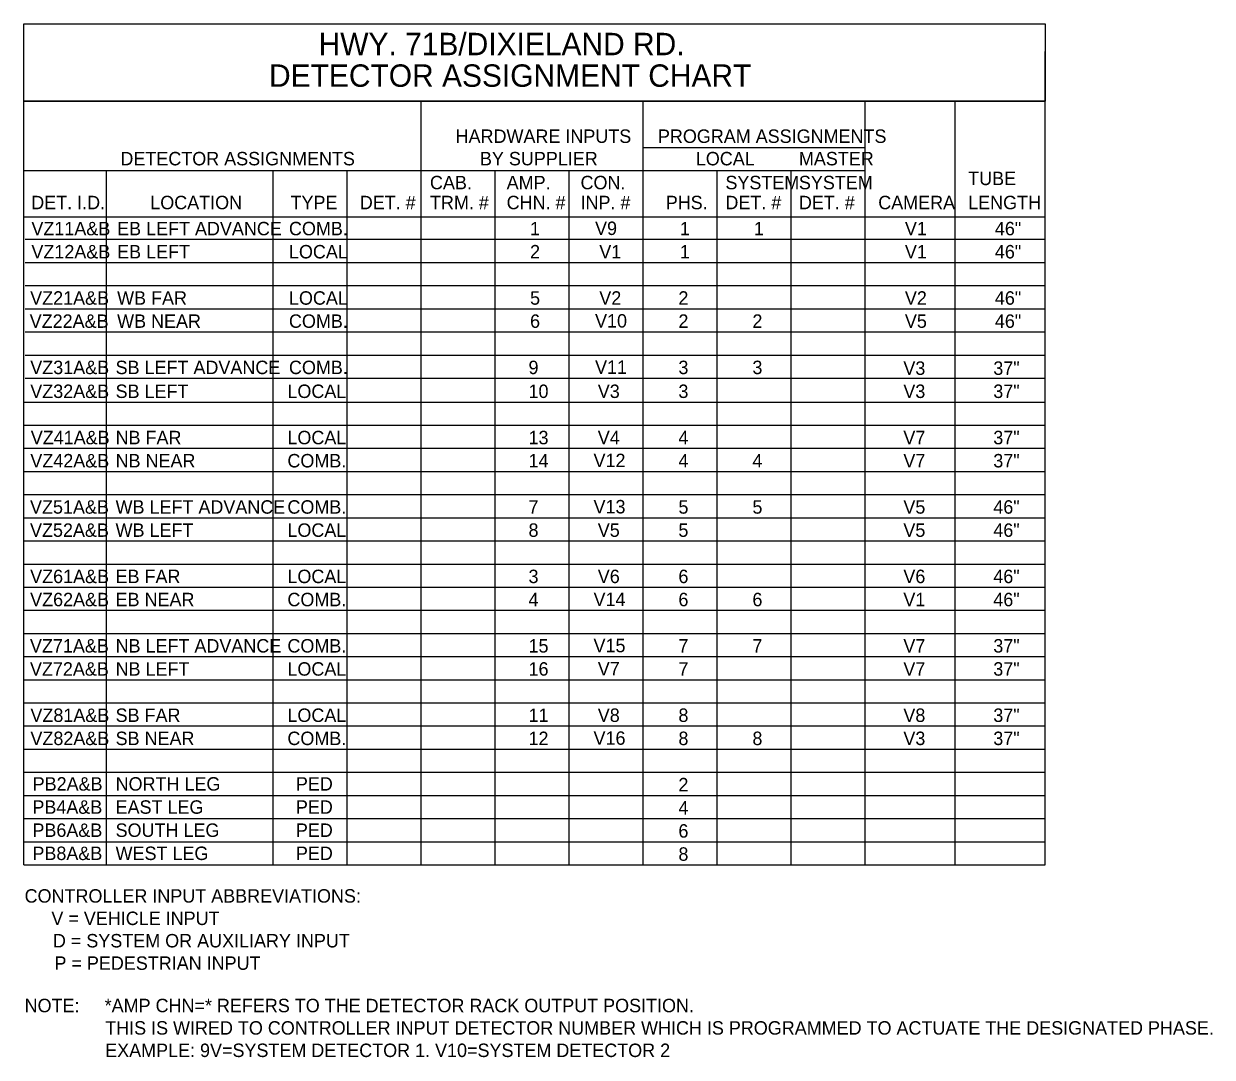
# Model space of a CAD drawing. Extents: x -15.7 to 19.3, y -1.4 to 10.8.
# Drawn here: x -15.71 to -8.64, y -1.45 to 4.7 of the extents above; entities that cross this region are included whole.
import ezdxf

# ---------------------------------------------------------------- set-up
doc = ezdxf.new("R2010")
doc.units = 0
for name, color, linetype in [('TBLBDR', 7, 'Continuous'), ('TBLLINE', 7, 'Continuous'), ('TBLTEXT', 7, 'Continuous'), ('TEXT', 7, 'Continuous'), ('TITEXT', 7, 'Continuous')]:
    doc.layers.add(name, color=color, linetype=linetype)

msp = doc.modelspace()

# ---------------------------------------------------------------- linework, layer by layer
at = {"layer": 'TBLBDR'}
for p, q in [((-15.7146, -0.303), (-15.7146, 4.5377)), ((-9.6309, -0.303), (-9.6309, 4.5377)), ((-15.7146, 4.2424), (-9.6309, 4.2424)), ((-13.3469, -0.303), (-13.3469, 4.2424)), ((-12.0246, -0.303), (-12.0246, 4.2424)), ((-10.7023, -0.303), (-10.7023, 4.2424)), ((-10.1666, -0.303), (-10.1666, 4.2424)), ((-12.0246, 3.9669), (-10.7023, 3.9669)), ((-15.7146, 3.8292), (-10.7023, 3.8292)), ((-15.7146, 3.5537), (-9.6309, 3.5537)), ((-15.7146, 0.2479), (-9.6309, 0.2479)), ((-15.7146, -0.303), (-9.6309, -0.303))]:
    msp.add_line(p, q, dxfattribs=at)
msp.add_lwpolyline([(-15.7146, 4.7035), (-9.6309, 4.7035), (-9.6309, 4.2424), (-15.7146, 4.2424)], close=True, dxfattribs=at)
at = {"layer": 'TBLLINE'}
for p, q in [((-15.2215, -0.303), (-15.2215, 3.8292)), ((-14.2285, -0.303), (-14.2285, 3.8292)), ((-13.7877, -0.303), (-13.7877, 3.8292)), ((-12.9062, -0.303), (-12.9062, 3.8292)), ((-12.4654, -0.303), (-12.4654, 3.8292)), ((-11.5839, -0.303), (-11.5839, 3.8292)), ((-11.1431, -0.303), (-11.1431, 3.8292)), ((-15.7054, 3.4204), (-9.6309, 3.4204)), ((-15.7054, 3.2826), (-9.6309, 3.2826)), ((-15.7054, 3.1449), (-9.6309, 3.1449)), ((-15.7054, 3.0071), (-9.6309, 3.0071)), ((-15.7054, 2.8694), (-9.6309, 2.8694)), ((-15.7054, 2.7317), (-9.6309, 2.7317)), ((-15.7054, 2.5939), (-9.6309, 2.5939)), ((-15.7146, 2.4518), (-9.6309, 2.4518)), ((-15.7146, 2.314), (-9.6309, 2.314)), ((-15.7146, 2.1763), (-9.6309, 2.1763)), ((-15.7146, 2.0385), (-9.6309, 2.0385)), ((-15.7146, 1.9008), (-9.6309, 1.9008)), ((-15.7146, 1.7631), (-9.6309, 1.7631)), ((-15.7146, 1.6253), (-9.6309, 1.6253)), ((-15.7146, 1.4876), (-9.6309, 1.4876)), ((-15.7146, 1.3498), (-9.6309, 1.3498)), ((-15.7146, 1.2121), (-9.6309, 1.2121)), ((-15.7146, 1.0744), (-9.6309, 1.0744)), ((-15.7146, 0.9366), (-9.6309, 0.9366)), ((-15.7146, 0.7989), (-9.6309, 0.7989)), ((-15.7146, 0.6611), (-9.6309, 0.6611)), ((-15.7146, 0.5234), (-9.6309, 0.5234)), ((-15.7146, 0.3857), (-9.6309, 0.3857)), ((-15.7146, 0.1102), (-9.6309, 0.1102)), ((-15.7146, -0.0276), (-9.6309, -0.0276)), ((-15.7146, -0.1653), (-9.6309, -0.1653))]:
    msp.add_line(p, q, dxfattribs=at)

# ---------------------------------------------------------------- texts
at = {"layer": 'TBLTEXT'}
for s, height, p in [('HARDWARE INPUTS', 0.079999, (-13.1425, 3.9943)), ('PROGRAM ASSIGNMENTS', 0.079999, (-11.9375, 3.9943)), ('DETECTOR ASSIGNMENTS', 0.079999, (-15.1389, 3.8607)), ('BY SUPPLIER', 0.079999, (-12.9975, 3.8607)), ('LOCAL', 0.08, (-11.7117, 3.8607)), ('MASTER', 0.08, (-11.0979, 3.8607)), ('TUBE', 0.08, (-10.0896, 3.7431)), ('CAB.', 0.08, (-13.2952, 3.7183)), ('AMP.', 0.08, (-12.8385, 3.7183)), ('CON.', 0.08, (-12.3984, 3.7183)), ('SYSTEM', 0.08, (-11.5355, 3.7183)), ('SYSTEM', 0.08, (-11.0979, 3.7183)), ('DET. I.D.', 0.08, (-15.67, 3.5995)), ('LOCATION', 0.08, (-14.9611, 3.5995)), ('TYPE', 0.08, (-14.1257, 3.5995)), ('DET. #', 0.08, (-13.7131, 3.5995)), ('TRM. #', 0.08, (-13.2952, 3.5995)), ('CHN. #', 0.08, (-12.8385, 3.5995)), ('INP. #', 0.08, (-12.3984, 3.5995)), ('PHS.', 0.08, (-11.8909, 3.5995)), ('DET. #', 0.08, (-11.5355, 3.5995)), ('DET. #', 0.08, (-11.0979, 3.5995)), ('CAMERA', 0.08, (-10.6253, 3.5995)), ('LENGTH', 0.08, (-10.0896, 3.5995)), ('CONTROLLER INPUT ABBREVIATIONS:', 0.079999, (-15.7096, -0.5281)), ('V = VEHICLE INPUT', 0.079999, (-15.5501, -0.6615)), ('D = SYSTEM OR AUXILIARY INPUT', 0.079999, (-15.541, -0.7948)), ('P = PEDESTRIAN INPUT', 0.079999, (-15.5319, -0.9281)), ('NOTE:', 0.08, (-15.7096, -1.1805)), ('*AMP CHN=* REFERS TO THE DETECTOR RACK OUTPUT POSITION.', 0.079999, (-15.2327, -1.1805)), ('THIS IS WIRED TO CONTROLLER INPUT DETECTOR NUMBER WHICH IS PROGRAMMED TO ACTUATE THE DESIGNATED PHASE.', 0.0799994, (-15.2296, -1.3138)), ('EXAMPLE: 9V=SYSTEM DETECTOR 1. V10=SYSTEM DETECTOR 2', 0.079999, (-15.2296, -1.4472))]:
    msp.add_text(s, height=height, dxfattribs=at).set_placement(p)
at = {"layer": 'TEXT'}
for s, height, p in [('VZ11A&B', 0.08, (-15.669, 3.4444)), ('EB LEFT ADVANCE', 0.079999, (-15.1585, 3.4444)), ('COMB.', 0.08, (-14.1351, 3.4444)), ('1', 0.08, (-12.6991, 3.4444)), ('V9', 0.08, (-12.3119, 3.4461)), ('1', 0.08, (-11.8063, 3.4444)), ('1', 0.08, (-11.3655, 3.4444)), ('V1', 0.08, (-10.4665, 3.4444)), ('46"', 0.08, (-9.9307, 3.4444)), ('VZ12A&B', 0.08, (-15.669, 3.3067)), ('EB LEFT', 0.08, (-15.1585, 3.3067)), ('LOCAL', 0.08, (-14.1351, 3.3067)), ('2', 0.08, (-12.6991, 3.3067)), ('V1', 0.08, (-12.2866, 3.3067)), ('1', 0.08, (-11.8063, 3.3067)), ('V1', 0.08, (-10.4665, 3.3067)), ('46"', 0.08, (-9.9307, 3.3067)), ('VZ21A&B', 0.08, (-15.6764, 3.0312)), ('WB FAR', 0.08, (-15.1585, 3.0312)), ('LOCAL', 0.08, (-14.1351, 3.0312)), ('5', 0.08, (-12.6991, 3.0312)), ('V2', 0.08, (-12.2866, 3.0312)), ('2', 0.08, (-11.8154, 3.0312)), ('V2', 0.08, (-10.4665, 3.0312)), ('46"', 0.08, (-9.9307, 3.0312)), ('VZ22A&B', 0.08, (-15.6793, 2.8935)), ('WB NEAR', 0.08, (-15.1585, 2.8935)), ('COMB.', 0.08, (-14.1351, 2.8935)), ('6', 0.08, (-12.6991, 2.8935)), ('V10', 0.08, (-12.3119, 2.8952)), ('2', 0.08, (-11.8154, 2.8935)), ('2', 0.08, (-11.3747, 2.8935)), ('V5', 0.08, (-10.4665, 2.8935)), ('46"', 0.08, (-9.9307, 2.8935)), ('VZ31A&B', 0.08, (-15.6758, 2.618)), ('SB LEFT ADVANCE', 0.079999, (-15.1676, 2.618)), ('COMB.', 0.08, (-14.1351, 2.618)), ('9', 0.08, (-12.7082, 2.618)), ('V11', 0.08, (-12.3119, 2.6197)), ('3', 0.08, (-11.8154, 2.618)), ('3', 0.08, (-11.3747, 2.618)), ('V3', 0.08, (-10.4756, 2.6136)), ('37"', 0.08, (-9.9399, 2.6136)), ('VZ32A&B', 0.08, (-15.6758, 2.4759)), ('SB LEFT', 0.08, (-15.1676, 2.4759)), ('LOCAL', 0.08, (-14.1442, 2.4759)), ('10', 0.08, (-12.7082, 2.4759)), ('V3', 0.08, (-12.2957, 2.4759)), ('3', 0.08, (-11.8154, 2.4759)), ('V3', 0.08, (-10.4756, 2.4759)), ('37"', 0.08, (-9.9399, 2.4759)), ('VZ41A&B', 0.08, (-15.6728, 2.2004)), ('NB FAR', 0.08, (-15.1676, 2.2004)), ('LOCAL', 0.08, (-14.1442, 2.2004)), ('13', 0.08, (-12.7082, 2.2004)), ('V4', 0.08, (-12.2957, 2.2004)), ('4', 0.08, (-11.8154, 2.2004)), ('V7', 0.08, (-10.4756, 2.2004)), ('37"', 0.08, (-9.9399, 2.2004)), ('VZ42A&B', 0.08, (-15.6755, 2.0626)), ('NB NEAR', 0.08, (-15.1676, 2.0626)), ('COMB.', 0.08, (-14.1442, 2.0626)), ('14', 0.08, (-12.7082, 2.0626)), ('V12', 0.08, (-12.3211, 2.0643)), ('4', 0.08, (-11.8154, 2.0626)), ('4', 0.08, (-11.3747, 2.0626)), ('V7', 0.08, (-10.4756, 2.0626)), ('37"', 0.08, (-9.9399, 2.0626)), ('VZ51A&B', 0.08, (-15.6773, 1.7872)), ('WB LEFT ADVANCE', 0.079999, (-15.1676, 1.7872)), ('COMB.', 0.08, (-14.1442, 1.7872)), ('7', 0.08, (-12.7082, 1.7872)), ('V13', 0.08, (-12.3211, 1.7889)), ('5', 0.08, (-11.8154, 1.7872)), ('5', 0.08, (-11.3747, 1.7872)), ('V5', 0.08, (-10.4756, 1.7872)), ('46"', 0.08, (-9.9399, 1.7872)), ('VZ52A&B', 0.08, (-15.6773, 1.6494)), ('WB LEFT', 0.08, (-15.1676, 1.6494)), ('LOCAL', 0.08, (-14.1442, 1.6494)), ('8', 0.08, (-12.7082, 1.6494)), ('V5', 0.08, (-12.2957, 1.6494)), ('5', 0.08, (-11.8154, 1.6494)), ('V5', 0.08, (-10.4756, 1.6494)), ('46"', 0.08, (-9.9399, 1.6494)), ('VZ61A&B', 0.08, (-15.6766, 1.3739)), ('EB FAR', 0.08, (-15.1676, 1.3739)), ('LOCAL', 0.08, (-14.1442, 1.3739)), ('3', 0.08, (-12.7082, 1.3739)), ('V6', 0.08, (-12.2957, 1.3739)), ('6', 0.08, (-11.8154, 1.3739)), ('V6', 0.08, (-10.4756, 1.3739)), ('46"', 0.08, (-9.9399, 1.3739)), ('VZ62A&B', 0.08, (-15.6766, 1.2362)), ('EB NEAR', 0.08, (-15.1676, 1.2362)), ('COMB.', 0.08, (-14.1442, 1.2362)), ('4', 0.08, (-12.7082, 1.2362)), ('V14', 0.08, (-12.3211, 1.2379)), ('6', 0.08, (-11.8154, 1.2362)), ('6', 0.08, (-11.3747, 1.2362)), ('V1', 0.08, (-10.4756, 1.2362)), ('46"', 0.08, (-9.9399, 1.2362)), ('VZ71A&B', 0.08, (-15.6777, 0.9607)), ('NB LEFT ADVANCE', 0.079999, (-15.1676, 0.9607)), ('COMB.', 0.08, (-14.1442, 0.9607)), ('15', 0.08, (-12.7082, 0.9607)), ('V15', 0.08, (-12.3211, 0.9624)), ('7', 0.08, (-11.8154, 0.9607)), ('7', 0.08, (-11.3747, 0.9607)), ('V7', 0.08, (-10.4756, 0.9607)), ('37"', 0.08, (-9.9399, 0.9607)), ('VZ72A&B', 0.08, (-15.6777, 0.823)), ('NB LEFT', 0.08, (-15.1676, 0.823)), ('LOCAL', 0.08, (-14.1442, 0.823)), ('16', 0.08, (-12.7082, 0.823)), ('V7', 0.08, (-12.2957, 0.8247)), ('7', 0.08, (-11.8154, 0.823)), ('V7', 0.08, (-10.4756, 0.823)), ('37"', 0.08, (-9.9399, 0.823)), ('VZ81A&B', 0.08, (-15.6749, 0.5475)), ('SB FAR', 0.08, (-15.1676, 0.5475)), ('LOCAL', 0.08, (-14.1442, 0.5475)), ('11', 0.08, (-12.7082, 0.5475)), ('V8', 0.08, (-12.2957, 0.5475)), ('8', 0.08, (-11.8154, 0.5475)), ('V8', 0.08, (-10.4756, 0.5475)), ('37"', 0.08, (-9.9399, 0.5475)), ('VZ82A&B', 0.08, (-15.6749, 0.4098)), ('SB NEAR', 0.08, (-15.1676, 0.4098)), ('COMB.', 0.08, (-14.1442, 0.4098)), ('12', 0.08, (-12.7082, 0.4098)), ('V16', 0.08, (-12.3211, 0.4115)), ('8', 0.08, (-11.8154, 0.4098)), ('8', 0.08, (-11.3747, 0.4098)), ('V3', 0.08, (-10.4756, 0.4098)), ('37"', 0.08, (-9.9399, 0.4098)), ('PB2A&B', 0.08, (-15.6615, 0.1387)), ('NORTH LEG', 0.08, (-15.1676, 0.1387)), ('PED', 0.08, (-14.0939, 0.1387)), ('2', 0.08, (-11.8154, 0.1343)), ('PB4A&B', 0.08, (-15.6631, 0.0009)), ('EAST LEG', 0.08, (-15.1676, 0.0009)), ('PED', 0.08, (-14.0939, 0.0009)), ('4', 0.08, (-11.8154, -0.0035)), ('PB6A&B ', 0.08, (-15.6631, -0.1368)), ('SOUTH LEG', 0.08, (-15.1676, -0.1368)), ('PED', 0.08, (-14.0939, -0.1368)), ('6', 0.08, (-11.8154, -0.1412)), ('PB8A&B', 0.08, (-15.6631, -0.2745)), ('WEST LEG', 0.08, (-15.1676, -0.2745)), ('PED', 0.08, (-14.0939, -0.2745)), ('8', 0.08, (-11.8154, -0.2789))]:
    msp.add_text(s, height=height, dxfattribs=at).set_placement(p)
at = {"layer": 'TITEXT'}
for s, p in [('HWY. 71B/DIXIELAND RD.', (-13.9584, 4.5163)), ('DETECTOR ASSIGNMENT CHART', (-14.2537, 4.3284))]:
    msp.add_text(s, height=0.133332, dxfattribs=at).set_placement(p)

doc.saveas('drawing.dxf')
